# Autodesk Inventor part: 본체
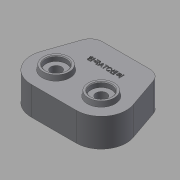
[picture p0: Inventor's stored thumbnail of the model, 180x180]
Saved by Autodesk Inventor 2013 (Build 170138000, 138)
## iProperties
Created: 2014-12
Part Number: 본체
Material: 일반
Document SubType Name: Modeling
Designer: WINDOWS7
Density: 1 g/cm^3
Author: WINDOWS7
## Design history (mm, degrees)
sketch "스케치1"
  geometry: 1 further point
sketch "스케치2"
  geometry: L1 (0, 0)-(94, 0); L2 (0, 0)-(-36.002, -104.527); L3 (94, 0)-(130.002, -104.527); L4 (130.002, -104.527)-(-36.002, -104.527); L5 (47, -36)-(4.722, -78.278); L6 (47, -36)-(47, -104.527); L7 (47, -36)-(91.638, -80.638); L8 (-4.181, -12.138)-(-19.565, -56.803); L9 (14.473, -104.527)-(79.527, -104.527); L10 (113.565, -56.803)-(98.181, -12.138); L11 (12.838, 0)-(81.162, 0); L12 (0.547, -13.767)-(-14.837, -58.432); L13 (14.473, -99.527)-(79.527, -99.527); L14 (108.837, -58.432)-(93.453, -13.767); L15 (12.838, -5)-(81.162, -5); A1 r 46 centre (47, -36) between (14.473, -68.527) and (79.527, -68.527); A2 r 18 centre (12.838, -18) between (12.838, 0) and (-4.181, -12.138); A3 r 18 centre (81.162, -18) between (98.181, -12.138) and (81.162, 0); A4 r 36 centre (14.473, -68.527) between (-19.565, -56.803) and (14.473, -104.527); A5 r 36 centre (79.527, -68.527) between (79.527, -104.527) and (113.565, -56.803); A6 r 31 centre (14.473, -68.527) between (-14.837, -58.432) and (14.473, -99.527); A7 r 13 centre (12.838, -18) between (12.838, -5) and (0.547, -13.767); A8 r 31 centre (79.527, -68.527) between (79.527, -99.527) and (108.837, -58.432); A9 r 13 centre (81.162, -18) between (93.453, -13.767) and (81.162, -5); 1 further point
  constraints: 30 end point, 19 point on circle, 11 tangent, 10 point on line, 9 centre point, 5 parallel, 2 midpoint, 1 collinear, 1 equal length, 1 equal radius, 1 horizontal, 1 vertical alignment
  dimensions: "d0" = 94 distance of L1.start L1.end; "d3" = 46 radius of A1; "d4" = 36 distance from line of L5.start L1; "d5" = 90 deg angle of L7 L5; "d6" = 45 deg angle of L6 L5; "d9" = 18 radius of A3; "d10" = 36 radius of A5; "d15" = 5 radial gap between concentric circles of A4 A6; "d16" = 5 distance between parallel lines of L15 L11; "d17" = 5 distance between parallel lines of L3 L14; "d18" = 5 radial gap between concentric circles of A8 A5; "d19" = 5 distance between parallel lines of L9 L13; "d20" = 5 distance between parallel lines of L2 L12
extrude "돌출1" new body sketch "스케치2" distance "d13" = 41; taper "d14" = 0 deg
extrude "돌출2" cut sketch "스케치2" distance "d21" = 31; taper "d22" = 0 deg
sketch "스케치6"
  geometry: L1 (-81.162, -5)-(-12.838, -5) reference; L2 (-14.473, -99.527)-(-79.527, -99.527) reference; L3 (-81.162, 0)-(-12.838, 0) reference; L4 (-108.837, -58.432)-(-93.453, -13.767) reference; L5 (-47, -5)-(-47, -99.527); L6 (-0.547, -13.767)-(14.837, -58.432) reference; A1 r 8 centre (-98.7, -29) between (-101.305, -36.564) and (-96.095, -21.436); A2 r 8 centre (-47, -99.527) between (-39, -99.527) and (-55, -99.527); A3 r 8 centre (4.7, -29) between (2.095, -21.436) and (7.305, -36.564); 1 further point
  constraints: 8 point on line, 6 point on circle, 3 centre point, 2 end point, 2 midpoint, 1 coincident
  dimensions: "d23" = 8 radius of A1; "d24" = 29 distance from line of A1.centre L3; "d25" = 8 radius of A2; "d26" = 8 radius of A3; "d27" = 29 distance from line of L3 A3.centre
extrude "돌출3" join sketch "스케치6" distance "d28" = 31; taper "d29" = 0 deg
sketch "스케치7"
  geometry: L1 (-81.162, -5)-(-12.838, -5) reference; L2 (-14.473, -104.527)-(-79.527, -104.527) reference; L3 (-47, -36)-(-113.79, -102.79); L4 (-47, -36)-(36.714, -119.714); L5 (-47, -36)-(-47, -104.527); L6 (-81.162, 0)-(-12.838, 0) reference; A1 r 24 centre (-47, -36) between (-25.889, -47.416) and (-35.584, -57.111); A2 r 24 centre (-79.527, -68.527) between (-68.111, -47.416) and (-58.416, -57.111); A3 r 24 centre (-14.473, -68.527) between (-35.584, -57.111) and (-25.889, -47.416); 2 further points
  constraints: 8 point on circle, 6 end point, 3 centre point, 2 midpoint, 2 point on line, 1 vertical alignment
  dimensions: "d30" = 48 diameter of A1; "d32" = 48 diameter of A2; "d33" = 48 diameter of A3; "d34" = 36 distance from line of A2.centre L2; "d35" = 36 distance from line of A3.centre L2; "d36" = 90 deg angle of L4 L3; "d37" = 45 deg angle of L4 L5; "d78" = 36 distance from line of L3.start L6
extrude "돌출4" join sketch "스케치7" distance "d38" = 11; taper "d39" = 0 deg
sketch "스케치8"
  geometry: C1 r 20 at (-47, -36); C2 r 17.5 at (-79.527, -68.527); C3 r 17.5 at (-14.473, -68.527); A1 r 24 centre (-14.473, -68.527) between (-35.584, -57.111) and (-25.889, -47.416) reference; A2 r 24 centre (-47, -36) between (-25.889, -47.416) and (-68.111, -47.416) reference; A3 r 24 centre (-79.527, -68.527) between (-68.111, -47.416) and (-58.416, -57.111) reference; 1 further point
  constraints: 3 centre point, 3 coincident
  dimensions: "d40" = 40 diameter of C1; "d41" = 35 diameter of C2; "d42" = 35 diameter of C3
extrude "돌출5" cut sketch "스케치8" distance "d43" = 11; taper "d44" = 0 deg
sketch "스케치9"
  geometry: C1 r 17.5 at (14.473, -68.527) reference; C2 r 17.5 at (79.527, -68.527) reference; C3 r 20 at (14.473, -68.527); C4 r 20 at (79.527, -68.527); 1 further point
  constraints: 2 centre point, 2 coincident
  dimensions: "d45" = 40 diameter of C3; "d46" = 40 diameter of C4
extrude "돌출6" join sketch "스케치9" distance "d47" = 7; taper "d48" = -10 deg
sketch "스케치10"
  geometry: C1 r 18.766 at (0, 0) reference; C2 r 15 at (0, 0); 1 further point
  constraints: 1 centre point, 1 coincident
  dimensions: "d49" = 30 diameter of C2
extrude "돌출7" cut sketch "스케치10" distance "d50" = 7; taper "d51" = 0 deg
sketch "스케치11"
  geometry: C1 r 18.766 at (0, 0) reference; C2 r 15 at (0, 0); 1 further point
  constraints: 1 centre point, 1 coincident
  dimensions: "d52" = 30 diameter of C2
extrude "돌출8" cut sketch "스케치11" distance "d53" = 7; taper "d54" = 0 deg
sketch "스케치12"
  geometry: C1 r 15 at (0, 0) reference; C2 r 7.75 at (0, 0); 1 further point
  constraints: 1 centre point, 1 coincident
  dimensions: "d55" = 15.5 diameter of C2
extrude "돌출9" cut sketch "스케치12" distance "d56" = 10; taper "d57" = 0 deg
sketch "스케치13"
  geometry: C1 r 15 at (0, 0) reference; C2 r 7.75 at (0, 0); 1 further point
  constraints: 1 centre point, 1 coincident
  dimensions: "d58" = 15.5 diameter of C2
extrude "돌출10" cut sketch "스케치13" distance "d59" = 10; taper "d60" = 0 deg
sketch "스케치14"
  geometry: L1 (81.162, 0)-(12.838, 0) reference; 3 further points
  constraints: 1 midpoint, 1 vertical alignment, 1 other
  dimensions: "d61" = 30 distance from line of point (47, -30) L1
feature "엠보싱1" sketch "스케치14" dims "d62" = 1, "d63" = 0
sketch "스케치15"
  geometry: C1 r 20 at (0, 0) reference; C2 r 10 at (0, 0); 1 further point
  constraints: 1 centre point, 1 coincident
  dimensions: "d64" = 20 diameter of C2
extrude "돌출11" cut sketch "스케치15" distance "d65" = 3; taper "d66" = 0 deg
sketch "스케치16"
  geometry: A1 r 8 centre (4.7, -29) between (2.095, -21.436) and (7.305, -36.564) reference; A2 r 8 centre (-47, -99.527) between (-39, -99.527) and (-55, -99.527) reference; A3 r 8 centre (-98.7, -29) between (-101.305, -36.564) and (-96.095, -21.436) reference; 4 further points
  constraints: 3 coincident
hole "구멍1" sketch "스케치16" at (4.7, -29), (-98.7, -29), (-47, -99.527) diameter "d67" = 4.134; stored, may be unused: countersink angle "d71" = 90 deg, drill point angle "d73" = 118 deg; dims "d68" = 20, "d69" = 4, "d70" = 2, "d72" = 23
fillet "모깎기1" dims "d74" = 3
fillet "모깎기2" dims "d75" = 3
fillet "모깎기3" dims "d76" = 0.3
fillet "모깎기4" dims "d77" = 0.1
chamfer "모따기1" distance "d79" = 1; stored, may be unused: second distance "d80" = 2, angle "d81" = 45 deg
chamfer "모따기2" distance "d82" = 1; stored, may be unused: second distance "d83" = 2, angle "d84" = 45 deg
chamfer "모따기3" distance "d85" = 1; stored, may be unused: second distance "d86" = 2, angle "d87" = 45 deg
node "솔리드1"
other parameters: "d1" = 18, "d2" = 18, "d7" = 36, "d8" = 36
